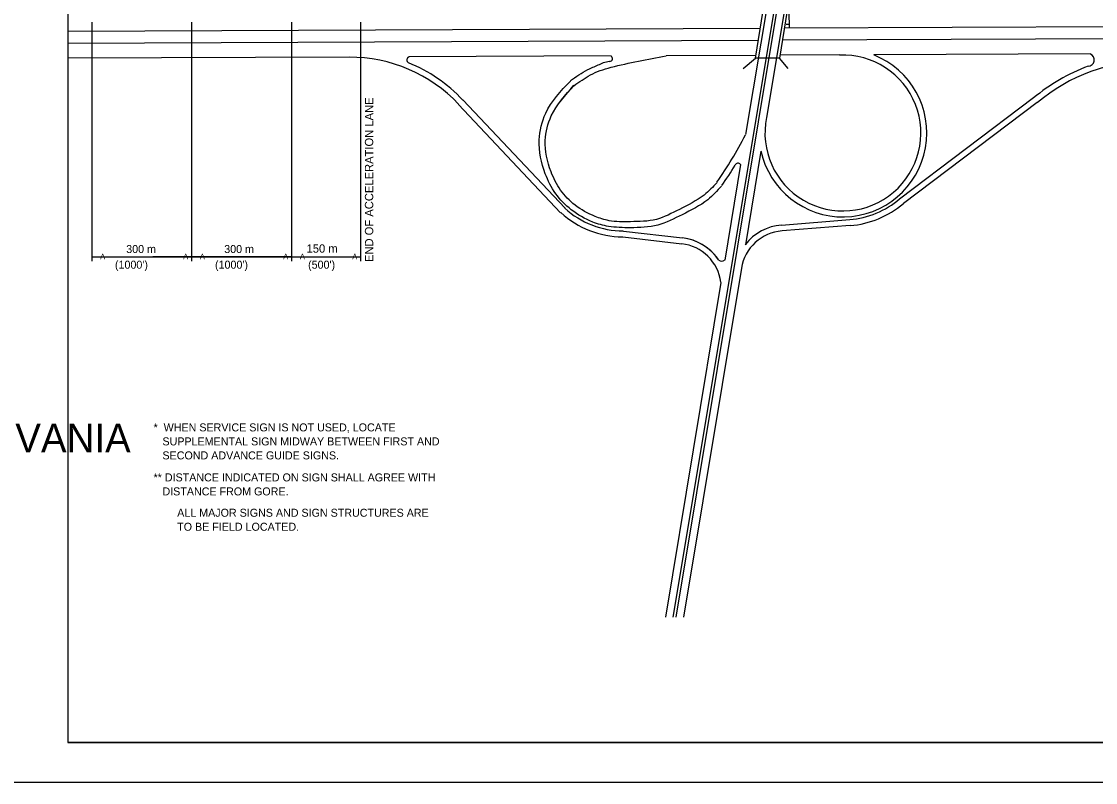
# Model space of a CAD drawing. Extents: x 640994 to 644422, y 298458 to 299646.
# Drawn here: x 643539.9 to 643942.6, y 299051.6 to 299337 of the extents above; entities that cross this region are included whole.
import ezdxf

# ---------------------------------------------------------------- set-up
doc = ezdxf.new("R2010")
doc.units = 0
for name, color, linetype in [('1', 7, 'Continuous'), ('2', 7, 'Continuous'), ('XCS-GRID-MIN', 7, 'Continuous')]:
    doc.layers.add(name, color=color, linetype=linetype)

msp = doc.modelspace()

# ---------------------------------------------------------------- linework, layer by layer
at = {"layer": '1'}
for p, q in [((643557.31, 299630.63), (643557.31, 299066.63)), ((644343.31, 299066.63), (643557.31, 299066.63)), ((643557.31, 299066.63), (644143.31, 299066.63))]:
    msp.add_line(p, q, dxfattribs=at)
at = {"layer": '2'}
for p, q in [((643862.56, 299584.52), (643784.06, 299113.64)), ((643863.56, 299584.52), (643785.19, 299113.64)), ((643831.06, 299372.02), (643819.19, 299300.89)), ((643822.81, 299363.27), (643811.31, 299294.52)), ((643815.06, 299323.14), (643817.94, 299341.02)), ((643826.94, 299341.02), (643824.06, 299323.14)), ((643827.56, 299340.27), (643827.69, 299334.64)), ((643566.31, 299336.64), (643566.31, 299247.14)), ((643603.69, 299336.64), (643603.69, 299247.14)), ((643641.19, 299336.64), (643641.19, 299247.14)), ((643667.06, 299336.64), (643667.06, 299247.14)), ((644343.31, 299336.65), (643825.94, 299334.39)), ((643816.81, 299334.27), (643557.31, 299333.14)), ((643817.94, 299334.27), (643817.94, 299334.27)), ((643824.81, 299334.39), (643824.81, 299334.39)), ((644343.31, 299332.27), (643825.19, 299329.89)), ((643827.69, 299335.77), (643826.56, 299335.77)), ((643816.06, 299329.77), (643557.31, 299328.64)), ((643817.19, 299329.77), (643817.19, 299329.77)), ((643824.06, 299329.89), (643824.06, 299329.89)), ((643760.94, 299324.02), (643685.19, 299323.64)), ((643815.06, 299324.14), (643781.56, 299324.02)), ((643823.19, 299324.27), (643823.19, 299324.27)), ((643846.69, 299324.39), (643824.31, 299324.27)), ((643940.69, 299324.77), (643859.44, 299324.39)), ((643662.81, 299323.52), (643557.31, 299323.14)), ((643557.31, 299323.14), (643557.31, 299323.14)), ((643810.44, 299319.27), (643815.06, 299323.14)), ((643824.06, 299323.14), (643815.06, 299323.14)), ((643827.31, 299319.27), (643824.06, 299323.14)), ((643919.31, 299308.27), (643869.06, 299270.39)), ((643703.81, 299305.89), (643742.06, 299265.27)), ((643705.44, 299307.52), (643743.69, 299267.02)), ((643920.69, 299306.52), (643870.56, 299268.77)), ((643817.06, 299288.39), (643811.31, 299253.27)), ((643809.44, 299283.39), (643803.56, 299247.52)), ((643824.88, 299260.65), (643850.43, 299262.67)), ((643850.61, 299260.43), (643825.06, 299258.41)), ((643765.31, 299256.27), (643787.44, 299253.64)), ((643765.56, 299258.39), (643787.69, 299255.89)), ((643566.31, 299248.77), (643641.19, 299248.77)), ((643641.19, 299248.77), (643589.19, 299248.77)), ((643641.19, 299248.77), (643667.06, 299248.77)), ((643809.81, 299244.52), (643788.06, 299113.64)), ((643802.06, 299239.14), (643781.31, 299113.64)), ((643781.31, 299113.64), (643781.31, 299113.64))]:
    msp.add_line(p, q, dxfattribs=at)
for centre, radius, start, end in [((643760.46, 299323.05), 1.05, 268.4832, 60.6541), ((643847.86, 299295.15), 31.46, 192.3822, 68.4017), ((643847.86, 299295.15), 29.22, 168.5632, 92.4201), ((643939.75, 299322.57), 2.38, 271.8811, 66.8776), ((643663.04, 299267.55), 55.99, 43.3195, 90.2526), ((643685.6, 299322.5), 1.19, 106.8392, 239.0676), ((643663.04, 299267.55), 58.23, 43.3195, 67.8501), ((643963.93, 299255.09), 69.42, 110.3144, 130), ((643963.94, 299255.09), 67.18, 90.2526, 130), ((643676.13, 299363.85), 151.98, 325.0122, 332.8209), ((643808.57, 299282.71), 1.14, 36.3436, 162.0571), ((643676.13, 299363.85), 154.22, 325.0122, 328.4086), ((643847.86, 299295.15), 32.58, 274.5223, 310.7112), ((643847.86, 299295.15), 34.82, 274.5221, 310.6656), ((643765.59, 299291.02), 34.82, 227.6536, 269.4877), ((643765.59, 299291.02), 32.58, 227.608, 269.9111), ((643826.38, 299241.67), 19.04, 94.5222, 142.4776), ((643785.49, 299236.93), 19.04, 35.8416, 83.3193), ((643785.49, 299236.93), 19.04, 33.5325, 83.3193), ((643826.38, 299241.67), 16.8, 94.522, 170.549), ((643785.49, 299236.93), 16.8, 7.7701, 83.3193), ((643802.39, 299248.88), 1.77, 234.1369, 309.4414)]:
    msp.add_arc(centre, radius, start, end, dxfattribs=at)
for points in [[(643747.06, 299312.89), (643753.19, 299316.89), (643756.81, 299318.52), (643760.94, 299319.77), (643781.56, 299324.02)], [(643745.69, 299314.77), (643752.19, 299318.89), (643756.06, 299320.64), (643760.31, 299322.02), (643760.44, 299322.02)], [(643802.31, 299275.27), (643797.19, 299270.14), (643787.56, 299264.52), (643778.44, 299260.64), (643768.19, 299259.64), (643759.94, 299260.14), (643754.06, 299261.77), (643746.06, 299266.39), (643740.19, 299272.39), (643736.31, 299279.89), (643734.06, 299292.52), (643736.44, 299302.52), (643745.69, 299314.64)], [(643800.69, 299276.64), (643795.81, 299271.89), (643786.56, 299266.52), (643777.94, 299262.77), (643768.19, 299261.89), (643760.19, 299262.27), (643754.94, 299263.89), (643747.44, 299268.14), (643742.06, 299273.77), (643738.44, 299280.64), (643736.31, 299292.39), (643738.56, 299301.52), (643747.06, 299313.02)], [(643800.69, 299276.64), (643795.81, 299271.89), (643786.56, 299266.52), (643777.94, 299262.77), (643768.19, 299261.89), (643760.19, 299262.27), (643754.94, 299263.89), (643747.44, 299268.14), (643742.06, 299273.77), (643738.44, 299280.64), (643736.31, 299292.39), (643738.56, 299301.52), (643747.06, 299312.89)]]:
    msp.add_spline(points, degree=3, dxfattribs=at)
at = {"layer": 'XCS-GRID-MIN'}
msp.add_lwpolyline([(643517.31, 299645.63), (644358.31, 299645.63), (644358.31, 299051.63), (643517.31, 299051.63)], close=True, dxfattribs=at)

# ---------------------------------------------------------------- texts
at = {"layer": '1'}
msp.add_text('COMMONWEALTH OF PENNSYLVANIA', height=10.7828, dxfattribs=at).set_placement((643314.9, 299175.36))
at = {"layer": '2'}
msp.add_text('END OF ACCELERATION LANE', height=3.1342, rotation=90, dxfattribs=at).set_placement((643671.81, 299246.77))
for s, height, p in [('300 m', 3, (643579.19, 299250.14)), ('300 m', 3, (643615.94, 299250.14)), ('150 m', 3.134, (643646.81, 299250.27)), ('A', 2.09, (643569.44, 299247.77)), ('A', 2.09, (643600.56, 299247.77)), ('A', 2.09, (643606.81, 299247.77)), ('A', 2.09, (643638.06, 299247.77)), ('A', 2.09, (643644.31, 299247.77)), ('A', 2.09, (643663.94, 299247.77)), ("(1000')", 3, (643574.97, 299244.27)), ("(1000')", 3, (643612.48, 299244.27)), ("(500')", 3, (643647.38, 299244.27)), ('*  WHEN SERVICE SIGN IS NOT USED, LOCATE', 3, (643589.44, 299183.27)), ('   SUPPLEMENTAL SIGN MIDWAY BETWEEN FIRST AND', 3, (643589.44, 299178.02)), ('   SECOND ADVANCE GUIDE SIGNS.', 3, (643589.44, 299172.77)), ('** DISTANCE INDICATED ON SIGN SHALL AGREE WITH', 3, (643589.44, 299164.52)), ('   DISTANCE FROM GORE.', 3, (643589.44, 299159.27)), ('ALL MAJOR SIGNS AND SIGN STRUCTURES ARE', 3, (643598.31, 299151.27)), ('TO BE FIELD LOCATED.', 3, (643598.31, 299146.02))]:
    msp.add_text(s, height=height, dxfattribs=at).set_placement(p)

doc.saveas('drawing.dxf')
